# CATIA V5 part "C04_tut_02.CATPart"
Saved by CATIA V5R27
Part number: Part1
Material "Aluminium": density 2710 kg/m3, Young's modulus 7e+10 Pa, Poisson ratio 0.346, thermal expansion 2.36e-05 1/K
Bounding box of the stored display mesh (mm): x 0 to 30, y -110 to 110, z 0 to 240
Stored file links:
  E:\_Deepak\2017_Deepak\CATIA\Resources\Tutorial Files\Tutorials\c04_catia_v5_6r2016_tut\C04_tut_02.CATPart
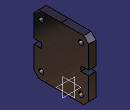
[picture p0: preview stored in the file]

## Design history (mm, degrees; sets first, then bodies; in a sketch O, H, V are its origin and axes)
Body1 (main body), material "Aluminium"
  Sketch1 on yz-plane, origin (0, 0, 0), H (0, 1, 0), V (0, 0, 1)
    line L1 (0, 0) -> (90, 0)
    point P1 (110, 0)
    line L2 (110, 20) -> (110, 110)
    point P2 (110, 220)
    line L3 (90, 0) -> (110, 20)
    point P3 (90, 0)
    point P4 (110, 20)
    point P5 (110, 120)
    line L4 (110, 110) -> (80, 110)
    line L5 (80, 110) -> (80, 130)
    line L6 (80, 130) -> (110, 130)
    point P6 (80, 110)
    point P7 (80, 130)
    point P8 (110, 110)
    point P9 (110, 130)
    axis line L7 (80, 120) -> (-216.0703, 120)
    point P10 (80, 120)
    point P12 (80, 130)
    point P13 (110, 130)
    point P14 (110, 220)
    line L8 (110, 220) -> (110, 130)
    point P15 (90, 240)
    line L9 (90, 240) -> (110, 220)
    point P16 (0, 240)
    line L10 (0, 240) -> (90, 240)
    reference intersected line E1 through (0, 0) direction (0, 1) from zx-plane
    point P19 (0, 0)
    construction line L11 through (0, 0) direction (-1, 0)
    construction line L12 through (0, 0) direction (0, 1)
    point P20 (-110, 0)
    point P21 (-110, 220)
    point P22 (-90, 0)
    point P23 (-110, 20)
    point P24 (-110, 120)
    point P25 (-80, 110)
    point P26 (-80, 130)
    point P27 (-110, 110)
    point P28 (-110, 130)
    point P29 (-80, 120)
    point P30 (-110, 130)
    point P31 (-110, 220)
    point P32 (-90, 240)
    point P33 (0, 240)
    line L13 (0, 0) -> (-90, 0)
    line L14 (-110, 20) -> (-110, 110)
    line L15 (-90, 0) -> (-110, 20)
    line L16 (-110, 110) -> (-80, 110)
    line L17 (-80, 110) -> (-80, 130)
    line L18 (-80, 130) -> (-110, 130)
    line L19 (-110, 220) -> (-110, 130)
    line L20 (-90, 240) -> (-110, 220)
    line L21 (0, 240) -> (-90, 240)
    circle A1 centre (80, 210) radius 10
    point P34 (80, 210)
    circle A2 centre (-80, 210) radius 10
    circle A3 centre (80, 30) radius 10
    circle A4 centre (-80, 30) radius 10
    distance P3 P1 = 20
    angle L3 L1 = 45
    distance L10 L1 = 240
    distance L2 L14 = 220
    distance P34 L10 = 30
    radius A1 = 10
    distance L5 L17 = 160
    distance L6 L4 = 20
    horizontal: L1 H, L4 H, L6 H, L7 H
    vertical: L2 V, L5 V
    coincidence: L1 P1, L2 P1, L2 P9, L2 P5, P34 L5, O P19, P9 P13, P16 P33, P28 P30
    equidistance: L4 L6 P5, P4 P2 P5
    midpoint: P10 L5
    symmetry: P6 P12 L7, P8 P13 L7, P4 P14 L7, L2 L8 L7, P3 P15 L7, L3 L9 L7, O P16 L7, L1 L10 L7, O P19 E1, H L11 E1, V L12 E1, P1 P20 E1, P2 P21 E1, P3 P22 E1, P4 P23 E1, P5 P24 E1, P6 P25 E1, P7 P26 E1, P8 P27 E1, P9 P28 E1, P10 P29 E1, P13 P30 E1, P14 P31 E1, P15 P32 E1, P16 P33 E1, L1 L13 E1, L2 L14 E1, L3 L15 E1, L4 L16 E1, L5 L17 E1, L6 L18 E1, L8 L19 E1, L9 L20 E1, L10 L21 E1, A1 A2 L12, A1 A3 L7, A2 A4 L7
  Pad1: profile Sketch1, direction (1, 0, 0), length 30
